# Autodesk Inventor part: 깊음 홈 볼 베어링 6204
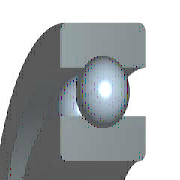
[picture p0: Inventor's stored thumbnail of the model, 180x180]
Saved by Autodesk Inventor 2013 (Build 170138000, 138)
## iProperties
IsCustomPart: 1
Created: 2012-02
Part Number: 깊음 홈 볼 베어링 6204
Material: 강철, 연강
Description: 깊은 그루부 볼 베어링
Document SubType Name: Modeling
Standard: JIS B 1521
Designer: mdu-01
Standards Organization: JIS
Language: ko-KR
Size Designation: 6204 20x47x14
Categories: <MemberInstance><Categories><Category DisplayName="샤프트 부품" InternalName="7f7aeb1f-a693-4053-b835-cee3144e0d98" Mnemonic="SHFT"><Category DisplayName="베어링" Inter
Density: 1 g/cm^3
Author: mdu-01
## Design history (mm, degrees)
sketch "스케치" dims "d0" = 7.02 (= -0.26 x WD + 0.26 x BD)
  geometry: L1 (3.49, 16.75)-(10.51, 16.75); L2 (7, 16.75)-(7, 13.24); L3 (7, 16.75)-(7, 20.26); L4 (4.392, 14.401)-(0, 14.401); L5 (0, 10)-(14, 10); L6 (4.392, 19.099)-(0, 19.099); L7 (0, 23.5)-(14, 23.5); L8 (14, 10)-(14, 14.401); L9 (9.608, 14.401)-(14, 14.401); L10 (9.608, 19.099)-(14, 19.099); L11 (14, 23.5)-(14, 19.099); L12 (-1.4, 0)-(8.4, 0) reference; L13 (0, -0.3)-(0, 5.3) reference
  constraints: 22 end point, 4 point on line, 2 collinear, 2 perpendicular, 2 symmetric about line, 1 midpoint, 1 parallel, 14 other
  dimensions: "d9" = 20 diameter of L5 L12 (= WD); "d11" = 47 diameter of L7 L12 (= BD); "d12" = 14 distance between parallel lines of L8 L13 (= KB); "d13" = 28.802 diameter of L9 L12 (= 0.326 x BD + 0.674 x WD)
revolve "본체" stored, may be unused: angle "d6" = 90 deg
revolve "볼" stored, may be unused: angle "d7" = 90 deg
pattern_circular "IDS_ARRAYBALL[SIMPL:T]" dims angle "d3" = 360 deg
body "Solid1"
fillet "모깎기1" dims "d1" = 1 (= KRS)
other parameters: "WD" = 20 [user parameter; used in 5 equation terms], "BD" = 47 [user parameter; used in 5 equation terms], "KB" = 14 [user parameter; used in 1 equation term], "KRS" = 1 [user parameter; used in 1 equation term], "d4" = 0, "d5" = 0, "d8" = 0, "d14" = 0, "d15" = 0, "BBA" = 0 [user parameter], "BC0" = 6550000 [user parameter], "BC" = 1.27e+07 [user parameter], "BR" = 23.5 (= 0.5 x BD) [user parameter]
